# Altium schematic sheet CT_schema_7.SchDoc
size 277 x 170 mm
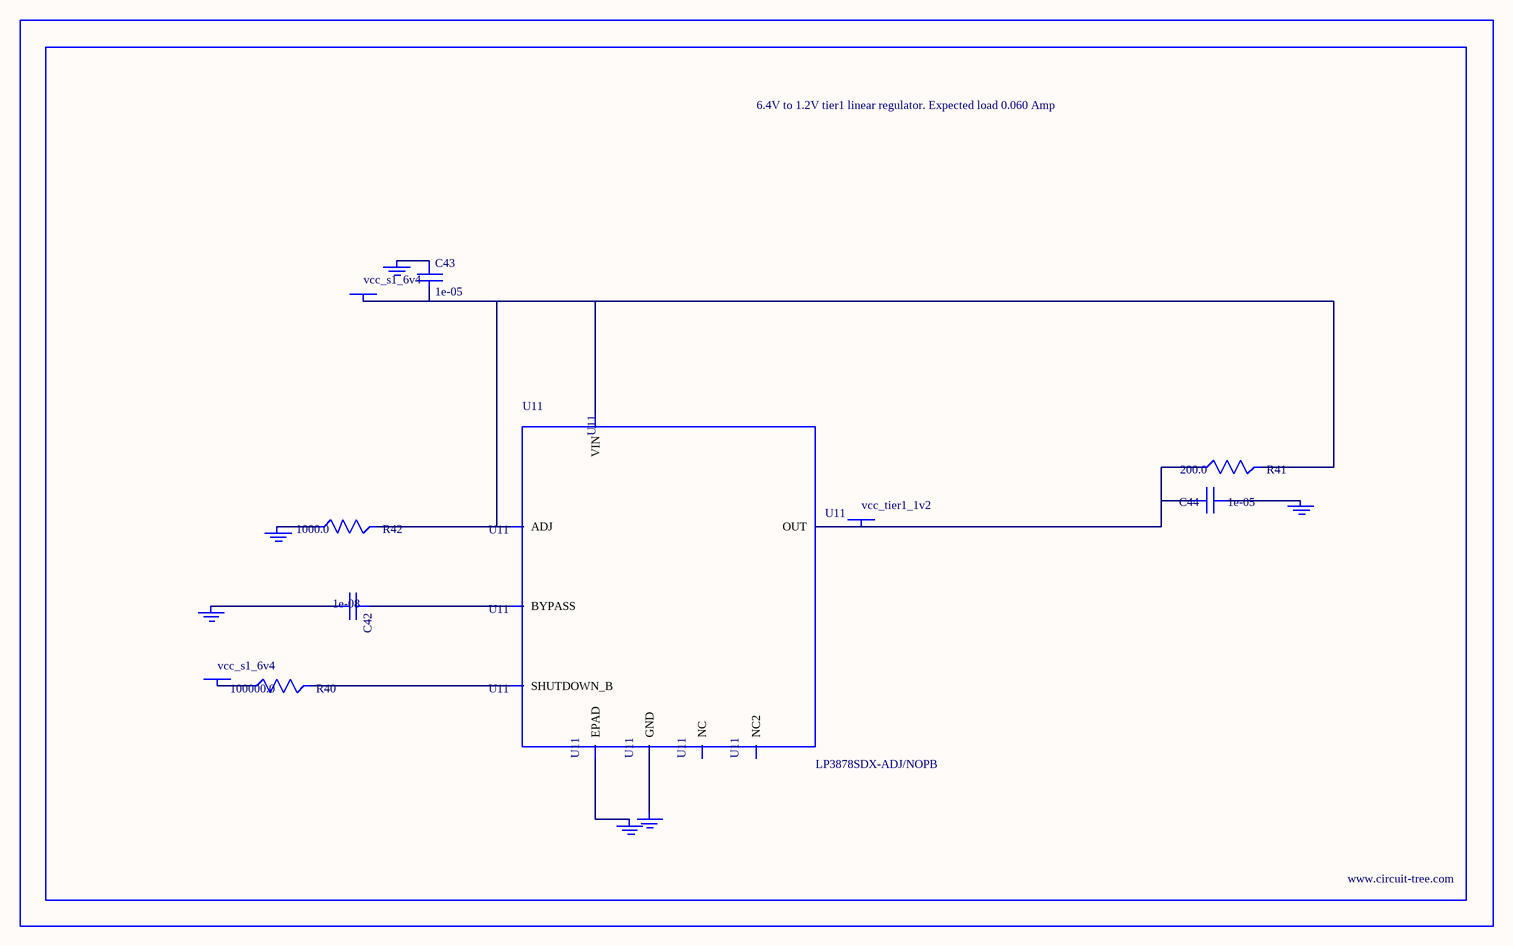
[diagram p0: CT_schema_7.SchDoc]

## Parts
BORDER6  (no value)
C42  1e-08  [C0402]
C43  1e-05  [C1206]
C44  1e-05  [C0805]
GND_INSTANCE_6_0  (no value)
GND_INSTANCE_6_1  (no value)
GND_INSTANCE_6_2  (no value)
GND_INSTANCE_6_3  (no value)
GND_INSTANCE_6_4  (no value)
GND_INSTANCE_6_5  (no value)
POWER_INSTANCE_6_0  vcc_s1_6v4
POWER_INSTANCE_6_1  vcc_s1_6v4
POWER_INSTANCE_6_2  vcc_tier1_1v2
R40  100000.0  [R0603]
R41  200.0  [R0603]
R42  1000.0  [R0603]
U11  LP3878SDX-ADJ/NOPB  [WSON-8]

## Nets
NetC42_1: C42.1 U11.1(BYPASS)
NetC42_2: C42.2 GND_INSTANCE_6_0.0(GND)
NetC43_1: C43.1 GND_INSTANCE_6_1.0(GND)
NetC43_2: C43.2 POWER_INSTANCE_6_0.0(PWR) R41.2 R42.2 U11.4(VIN) U11.6(ADJ)
NetC44_1: C44.1 GND_INSTANCE_6_2.0(GND)
NetC44_2: C44.2 POWER_INSTANCE_6_2.0(PWR) R41.1 U11.5(OUT)
NetGND_INSTANCE_6_3_0: GND_INSTANCE_6_3.0(GND) R42.1
NetGND_INSTANCE_6_4_0: GND_INSTANCE_6_4.0(GND) U11.PAD(EPAD)
NetGND_INSTANCE_6_5_0: GND_INSTANCE_6_5.0(GND) U11.3(GND)
NetPOWER_INSTANCE_6_1_0: POWER_INSTANCE_6_1.0(PWR) R40.1
NetR40_2: R40.2 U11.8(SHUTDOWN_B)

Not connected (* = marked no-connect by the designer): U11 2(NC) 7(NC2)

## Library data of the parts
BORDER6 = BORDER_PAGE6
C42 = C0402C103K3RAC
C43 = C1206C106K3RACTU
C44 = GRM219R60J106ME19D
GND_INSTANCE_6_0-GND_INSTANCE_6_5 = GND
POWER_INSTANCE_6_0-POWER_INSTANCE_6_2 = PWR
R40 = RC0603JR-07100KL
R41 = RC0603JR-07200RL
R42 = RC0603JR-071KL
